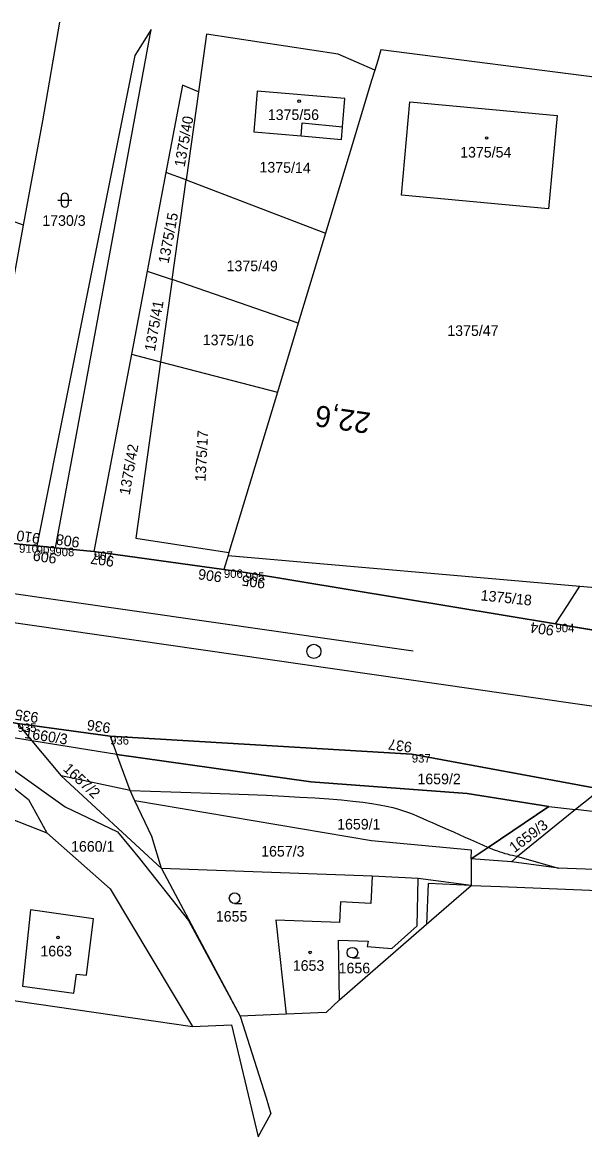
# Model space of a CAD drawing. Extents: x -757895 to -757311, y -1060303 to -1059942.
# Drawn here: x -757525.5 to -757445.9, y -1060221.2 to -1060063.5 of the extents above; entities that cross this region are included whole.
import ezdxf

# ---------------------------------------------------------------- set-up
doc = ezdxf.new("R2010")
doc.units = 0
for name, color, linetype in [('_hektaky', 7, 'Continuous'), ('_SO 102 hektometry', 7, 'Continuous'), ('Obvod stavby', 7, 'Continuous'), ('Vrstva 1', 7, 'Continuous'), ('Vrstva 53', 7, 'Continuous'), ('Vrstva 55', 7, 'Continuous'), ('Vrstva 56', 7, 'Continuous'), ('Vrstva 57', 7, 'Continuous'), ('Vrstva 58', 7, 'Continuous'), ('Vrstva 59', 7, 'Continuous'), ('Vrstva 60', 7, 'Continuous')]:
    doc.layers.add(name, color=color, linetype=linetype)

msp = doc.modelspace()

# ---------------------------------------------------------------- linework, layer by layer
at = {"layer": '_SO 102 hektometry'}
msp.add_circle((-757484.25, -1060152.51), 1, dxfattribs=at)
at = {"layer": 'Obvod stavby'}
for points in [[(-757420.49, -1060174.29), (-757417.66, -1060153.97), (-757419.22, -1060153.71), (-757450.04, -1060148.6), (-757493.93, -1060141.33), (-757496.99, -1060140.91), (-757515.4, -1060138.37), (-757520.85, -1060137.84), (-757523.49, -1060137.59), (-757525.99, -1060137.35), (-757528.28, -1060137.03), (-757533.01, -1060136.32), (-757534.03, -1060136.19), (-757535.86, -1060133.35), (-757568.62, -1060130.44), (-757606.63, -1060125.23), (-757624.32, -1060124.22), (-757624.54, -1060126.42), (-757639.93, -1060124.17), (-757687.19, -1060114.38)], [(-757686.64, -1060138.39), (-757635.44, -1060145.86), (-757634.26, -1060145.96), (-757632.1, -1060146.3), (-757543.88, -1060160.4), (-757542.9, -1060160.49), (-757535.01, -1060161.18), (-757533.6, -1060161.43), (-757526.21, -1060162.71), (-757513.1, -1060164.5), (-757470.38, -1060167.04), (-757443.58, -1060171.99), (-757420.49, -1060174.29)]]:
    msp.add_lwpolyline(points, dxfattribs=at)
at = {"layer": 'Vrstva 1'}
for p, q in [((-757429.32, -1060162.53), (-757720.62, -1060120.47)), ((-757576.18, -1060137.2), (-757470.2, -1060152.45))]:
    msp.add_line(p, q, dxfattribs=at)
at = {"layer": 'Vrstva 53'}
for points in [[(-757687.19, -1060114.38), (-757639.93, -1060124.17), (-757624.54, -1060126.42), (-757624.32, -1060124.22), (-757612.89, -1060124.84), (-757606.63, -1060125.23), (-757568.62, -1060130.44), (-757535.86, -1060133.35), (-757534.03, -1060136.19), (-757533.01, -1060136.32), (-757528.28, -1060137.03), (-757525.99, -1060137.35), (-757523.49, -1060137.59), (-757520.85, -1060137.84), (-757515.4, -1060138.37), (-757496.99, -1060140.91), (-757493.93, -1060141.33), (-757450.04, -1060148.6), (-757417.66, -1060153.97), (-757412.43, -1060151.61), (-757391.89, -1060154.81), (-757390.25, -1060143), (-757387.56, -1060158.16)], [(-757328.56, -1060183.46), (-757338.29, -1060184.85), (-757361.91, -1060181.63), (-757443.58, -1060171.99), (-757470.38, -1060167.04), (-757513.1, -1060164.5), (-757526.21, -1060162.71), (-757533.6, -1060161.43), (-757535.01, -1060161.18), (-757542.9, -1060160.49), (-757543.88, -1060160.4), (-757632.1, -1060146.3), (-757634.26, -1060145.96), (-757635.44, -1060145.86), (-757686.64, -1060138.39), (-757693.18, -1060137.43), (-757732.62, -1060131.67), (-757793.56, -1060122.78), (-757866, -1060118.97)], [(-757509.58, -1060173.65), (-757510.26, -1060172.2), (-757512.14, -1060167.1), (-757484.68, -1060170.98), (-757462.52, -1060172.6), (-757450.99, -1060174.46), (-757459.56, -1060180.26), (-757461.95, -1060181.88), (-757461.94, -1060180.64), (-757476.1, -1060179.3), (-757509.58, -1060173.65)]]:
    msp.add_lwpolyline(points, dxfattribs=at)
at = {"layer": 'Vrstva 55'}
for p, q in [((-757522.65, -1060077.4), (-757520.23, -1060063.47)), ((-757499.45, -1060065.15), (-757500.59, -1060073.29)), ((-757480.83, -1060068), (-757499.45, -1060065.15)), ((-757475.63, -1060070.26), (-757480.83, -1060068)), ((-757474.75, -1060067.35), (-757475.21, -1060068.86)), ((-757425.51, -1060073.71), (-757474.75, -1060067.35)), ((-757475.21, -1060068.86), (-757475.63, -1060070.26)), ((-757525.35, -1060092.2), (-757579.91, -1060072.75)), ((-757502.84, -1060072.35), (-757505.19, -1060084.71)), ((-757500.59, -1060073.29), (-757502.84, -1060072.35)), ((-757500.59, -1060073.29), (-757502.35, -1060085.79)), ((-757525.35, -1060092.2), (-757522.65, -1060077.4)), ((-757505.19, -1060084.71), (-757507.85, -1060098.68)), ((-757502.35, -1060085.79), (-757505.19, -1060084.71)), ((-757504.33, -1060099.89), (-757502.35, -1060085.79)), ((-757502.35, -1060085.79), (-757482.61, -1060093.33)), ((-757527.8, -1060105.72), (-757525.35, -1060092.2)), ((-757482.61, -1060093.33), (-757486.45, -1060106.04)), ((-757507.85, -1060098.68), (-757510.09, -1060110.45)), ((-757507.85, -1060098.68), (-757504.33, -1060099.89)), ((-757504.33, -1060099.89), (-757505.97, -1060111.52)), ((-757486.45, -1060106.04), (-757504.33, -1060099.89)), ((-757486.45, -1060106.04), (-757489.4, -1060115.81)), ((-757510.09, -1060110.45), (-757515.4, -1060138.37)), ((-757510.09, -1060110.45), (-757505.97, -1060111.52)), ((-757505.97, -1060111.52), (-757489.4, -1060115.81)), ((-757489.4, -1060115.81), (-757496.27, -1060138.53)), ((-757515.4, -1060138.37), (-757496.99, -1060140.91)), ((-757496.4, -1060138.94), (-757496.99, -1060140.91)), ((-757496.27, -1060138.53), (-757496.4, -1060138.94)), ((-757496.4, -1060138.94), (-757446.57, -1060143.26)), ((-757450.04, -1060148.6), (-757417.66, -1060153.97)), ((-757526.21, -1060162.71), (-757513.1, -1060164.5)), ((-757513.1, -1060164.5), (-757512.14, -1060167.1)), ((-757443.58, -1060171.99), (-757447.18, -1060174.91)), ((-757507.2, -1060178.7), (-757509.58, -1060173.65)), ((-757450.99, -1060174.46), (-757447.18, -1060174.91)), ((-757505.82, -1060183.25), (-757507.2, -1060178.7)), ((-757461.95, -1060181.88), (-757461.97, -1060185.63)), ((-757456.27, -1060182.28), (-757461.95, -1060181.88)), ((-757475.98, -1060184.31), (-757505.82, -1060183.25)), ((-757505.82, -1060183.25), (-757494.7, -1060204.13)), ((-757449.6, -1060183.18), (-757456.27, -1060182.28)), ((-757469.46, -1060184.66), (-757475.98, -1060184.31)), ((-757461.97, -1060185.63), (-757469.46, -1060184.66)), ((-757468.3, -1060191.14), (-757461.97, -1060185.63)), ((-757461.97, -1060185.63), (-757457.81, -1060185.8)), ((-757457.81, -1060185.8), (-757442.84, -1060186.4)), ((-757480.62, -1060201.84), (-757468.3, -1060191.14)), ((-757553.73, -1060197.99), (-757501.45, -1060205.62)), ((-757482.5, -1060203.63), (-757480.62, -1060201.84)), ((-757488.16, -1060203.86), (-757494.7, -1060204.13)), ((-757482.5, -1060203.63), (-757488.16, -1060203.86)), ((-757492.15, -1060221.2), (-757490.36, -1060217.94))]:
    msp.add_line(p, q, dxfattribs=at)
for points in [[(-757475.63, -1060070.26), (-757476.07, -1060071.71), (-757479.24, -1060082.21), (-757482.61, -1060093.33)], [(-757486.06, -1060079.54), (-757480.34, -1060080.05), (-757480.18, -1060078.28), (-757479.84, -1060074.24), (-757492.3, -1060073.2), (-757492.76, -1060078.99), (-757486.06, -1060079.54)], [(-757470.67, -1060074.74), (-757449.81, -1060076.66), (-757451.01, -1060089.85), (-757471.85, -1060087.93), (-757470.67, -1060074.74)], [(-757446.57, -1060143.26), (-757435.09, -1060144.26), (-757425.51, -1060073.71)], [(-757505.97, -1060111.52), (-757509.48, -1060136.47), (-757496.27, -1060138.53)], [(-757515.4, -1060138.37), (-757518.94, -1060138.03), (-757520.85, -1060137.84), (-757523.49, -1060137.59), (-757525.99, -1060137.35)], [(-757496.99, -1060140.91), (-757493.93, -1060141.33), (-757450.04, -1060148.6)], [(-757450.04, -1060148.6), (-757448.35, -1060146), (-757446.57, -1060143.26)], [(-757535.4, -1060164.4), (-757534.05, -1060166.5), (-757527.72, -1060171), (-757524.67, -1060173.45), (-757522.06, -1060178.2)], [(-757530.47, -1060164.08), (-757526.6, -1060169.42), (-757519.47, -1060174.52), (-757512.04, -1060178.07), (-757508.94, -1060181.82), (-757502, -1060190.6), (-757494.7, -1060204.13)], [(-757512.14, -1060167.1), (-757524.18, -1060165.15), (-757527.62, -1060164.59), (-757530.47, -1060164.08)], [(-757513.1, -1060164.5), (-757470.38, -1060167.04), (-757443.58, -1060171.99)], [(-757450.99, -1060174.46), (-757462.52, -1060172.6), (-757484.68, -1060170.98), (-757512.14, -1060167.1)], [(-757509.58, -1060173.65), (-757510.26, -1060172.2), (-757512.14, -1060167.1)], [(-757541.4, -1060170.7), (-757539.76, -1060171.25), (-757522.06, -1060178.2)], [(-757461.95, -1060181.88), (-757461.94, -1060180.64), (-757476.1, -1060179.3), (-757509.58, -1060173.65)], [(-757461.95, -1060181.88), (-757459.56, -1060180.26), (-757450.99, -1060174.46)], [(-757447.18, -1060174.91), (-757455.39, -1060181.56), (-757456.27, -1060182.28)], [(-757373.86, -1060183.46), (-757405.36, -1060179.78), (-757434.52, -1060176.38), (-757447.18, -1060174.91)], [(-757522.06, -1060178.2), (-757513.1, -1060186.11), (-757501.45, -1060205.62)], [(-757373.35, -1060185.99), (-757375.27, -1060185.92), (-757449.6, -1060183.18)], [(-757475.98, -1060184.31), (-757476.19, -1060188.18), (-757480.46, -1060187.96), (-757480.61, -1060190.87), (-757489.65, -1060190.56), (-757488.16, -1060203.86)], [(-757480.62, -1060201.84), (-757480.75, -1060193.37), (-757476.57, -1060193.52), (-757476.69, -1060194.3), (-757473.22, -1060194.56), (-757469.64, -1060191.34), (-757469.46, -1060184.66)], [(-757525.5, -1060199.9), (-757518.26, -1060200.9), (-757517.87, -1060198.2), (-757516.44, -1060198.33), (-757515.46, -1060190.37), (-757524.35, -1060189.08), (-757525.5, -1060199.9)], [(-757494.7, -1060204.13), (-757490.98, -1060215.68), (-757490.36, -1060217.94)], [(-757501.45, -1060205.62), (-757495.89, -1060205.36), (-757492.15, -1060221.2)]]:
    msp.add_lwpolyline(points, dxfattribs=at)
at = {"layer": 'Vrstva 56'}
for p, q in [((-757516.7, -1060115.45), (-757507.27, -1060064.51)), ((-757507.27, -1060064.51), (-757509.6, -1060068.17)), ((-757509.6, -1060068.17), (-757518.99, -1060115.13)), ((-757486.06, -1060079.54), (-757485.91, -1060077.7)), ((-757485.91, -1060077.7), (-757480.18, -1060078.28)), ((-757518.99, -1060115.13), (-757523.49, -1060137.59)), ((-757520.85, -1060137.84), (-757516.7, -1060115.45)), ((-757526.21, -1060162.71), (-757524.18, -1060165.15)), ((-757524.18, -1060165.15), (-757520.05, -1060170.1)), ((-757520.05, -1060170.1), (-757505.82, -1060183.25)), ((-757510.26, -1060172.2), (-757520.05, -1060170.1)), ((-757455.39, -1060181.56), (-757449.6, -1060183.18)), ((-757468.07, -1060185.38), (-757468.3, -1060191.14)), ((-757461.97, -1060185.63), (-757468.07, -1060185.38))]:
    msp.add_line(p, q, dxfattribs=at)
for points in [[(-757510.26, -1060172.2), (-757507.38, -1060172.29), (-757504.48, -1060172.38), (-757501.65, -1060172.48), (-757498.87, -1060172.57), (-757496.13, -1060172.67), (-757493.5, -1060172.78), (-757490.97, -1060172.88), (-757488.52, -1060173), (-757486.24, -1060173.12), (-757484.11, -1060173.25), (-757482.11, -1060173.39), (-757480.33, -1060173.53), (-757478.74, -1060173.69), (-757477.31, -1060173.85), (-757476.06, -1060174.03), (-757474.95, -1060174.21), (-757473.95, -1060174.41), (-757473.07, -1060174.62), (-757472.28, -1060174.84), (-757471.54, -1060175.07), (-757470.86, -1060175.32), (-757470.2, -1060175.57), (-757469.55, -1060175.85), (-757468.9, -1060176.13), (-757468.22, -1060176.43), (-757467.51, -1060176.74), (-757466.79, -1060177.06), (-757466.04, -1060177.39), (-757465.27, -1060177.73), (-757464.48, -1060178.07), (-757463.69, -1060178.43), (-757462.87, -1060178.79), (-757462.05, -1060179.15), (-757461.23, -1060179.52), (-757460.39, -1060179.89), (-757459.56, -1060180.26)], [(-757455.39, -1060181.56), (-757455.75, -1060181.49), (-757456.1, -1060181.41), (-757456.46, -1060181.33), (-757456.81, -1060181.23), (-757457.16, -1060181.14), (-757457.51, -1060181.03), (-757457.86, -1060180.92), (-757458.2, -1060180.8), (-757458.55, -1060180.68), (-757458.89, -1060180.54), (-757459.22, -1060180.41), (-757459.56, -1060180.26)]]:
    msp.add_lwpolyline(points, dxfattribs=at)
at = {"layer": 'Vrstva 58'}
for p, q in [((-757520.52, -1060088.64), (-757518.52, -1060088.64)), ((-757520.02, -1060088.14), (-757520.02, -1060089.14)), ((-757519.02, -1060088.14), (-757519.02, -1060089.14)), ((-757495.47, -1060188.19), (-757494.47, -1060188.19)), ((-757478.79, -1060195.9), (-757477.79, -1060195.9))]:
    msp.add_line(p, q, dxfattribs=at)
for centre in [(-757495.47, -1060187.44), (-757478.79, -1060195.15)]:
    msp.add_circle(centre, 0.75, dxfattribs=at)
for centre, start, end in [((-757519.52, -1060088.14), 0, 180), ((-757519.52, -1060089.14), 180, 0)]:
    msp.add_arc(centre, 0.5, start, end, dxfattribs=at)
at = {"layer": 'Vrstva 59'}
for centre in [(-757486.33, -1060074.63), (-757459.78, -1060079.84), (-757520.49, -1060193.01), (-757484.78, -1060195.12)]:
    msp.add_circle(centre, 0.175, dxfattribs=at)
at = {"layer": 'Vrstva 60'}
for p, q in [((-757523.49, -1060137.59), (-757523.49, -1060137.59)), ((-757520.85, -1060137.84), (-757520.85, -1060137.84)), ((-757515.4, -1060138.37), (-757515.4, -1060138.37)), ((-757496.99, -1060140.91), (-757496.99, -1060140.91)), ((-757493.93, -1060141.33), (-757493.93, -1060141.33)), ((-757450.04, -1060148.6), (-757450.04, -1060148.6)), ((-757513.1, -1060164.5), (-757513.1, -1060164.5)), ((-757470.38, -1060167.04), (-757470.38, -1060167.04))]:
    msp.add_line(p, q, dxfattribs=at)

# ---------------------------------------------------------------- texts
at = {"layer": '_hektaky'}
msp.add_text('22,6', height=3, rotation=171.8129, dxfattribs=at).set_placement((-757476.09, -1060118.76))
at = {"layer": 'Obvod stavby'}
for s, p in [('910', (-757522.92, -1060135.83)), ('908', (-757517.33, -1060136.37)), ('909', (-757520.58, -1060138.64)), ('907', (-757512.44, -1060139.08)), ('906', (-757497.19, -1060141.28)), ('905', (-757491.03, -1060142.17)), ('904', (-757450.17, -1060148.83)), ('935', (-757523.15, -1060161.17)), ('936', (-757512.95, -1060162.64)), ('937', (-757470.27, -1060165.37))]:
    msp.add_text(s, height=1.5, rotation=171.7882, dxfattribs=at).set_placement(p)
at = {"layer": 'Vrstva 57'}
for s, p in [('1375/56', (-757490.77, -1060077.3)), ('1375/54', (-757463.53, -1060082.61)), ('1730/3', (-757522.7, -1060092.28)), ('1375/49', (-757496.6, -1060098.7)), ('1375/47', (-757465.35, -1060107.86)), ('1659/2', (-757469.58, -1060171.31)), ('1659/1', (-757480.95, -1060177.72)), ('1660/1', (-757518.63, -1060180.86)), ('1657/3', (-757491.71, -1060181.55)), ('1655', (-757498.13, -1060190.76)), ('1663', (-757522.97, -1060195.68)), ('1653', (-757487.23, -1060197.72)), ('1656', (-757480.74, -1060198.08))]:
    msp.add_text(s, height=1.5, dxfattribs=at).set_placement(p)
for s, rotation, p in [('1375/40', 80, (-757502.55, -1060084.03)), ('1375/14', 359, (-757491.96, -1060084.71)), ('1375/15', 79, (-757504.83, -1060097.7)), ('1375/41', 80, (-757506.77, -1060110.13)), ('1375/16', 359, (-757499.99, -1060109.15)), ('1375/17', 87, (-757499.59, -1060128.49)), ('1375/42', 80, (-757510.34, -1060130.46)), ('1375/18', 354, (-757460.68, -1060145.28)), ('1660/3', 351, (-757525.3, -1060164.76)), ('1657/2', 317, (-757519.86, -1060169.27)), ('1659/3', 37, (-757455.86, -1060181.08))]:
    msp.add_text(s, height=1.5, rotation=rotation, dxfattribs=at).set_placement(p)
at = {"layer": 'Vrstva 60'}
for s, p in [('910', (-757525.99, -1060138.55)), ('909', (-757523.49, -1060138.79)), ('908', (-757520.85, -1060139.04)), ('907', (-757515.4, -1060139.57)), ('906', (-757496.99, -1060142.11)), ('905', (-757493.93, -1060142.53)), ('904', (-757450.04, -1060149.8)), ('935', (-757526.21, -1060163.91)), ('936', (-757513.1, -1060165.7)), ('937', (-757470.38, -1060168.24))]:
    msp.add_text(s, height=1.2, dxfattribs=at).set_placement(p)

doc.saveas('drawing.dxf')
